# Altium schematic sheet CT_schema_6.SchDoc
size 218 x 258 mm
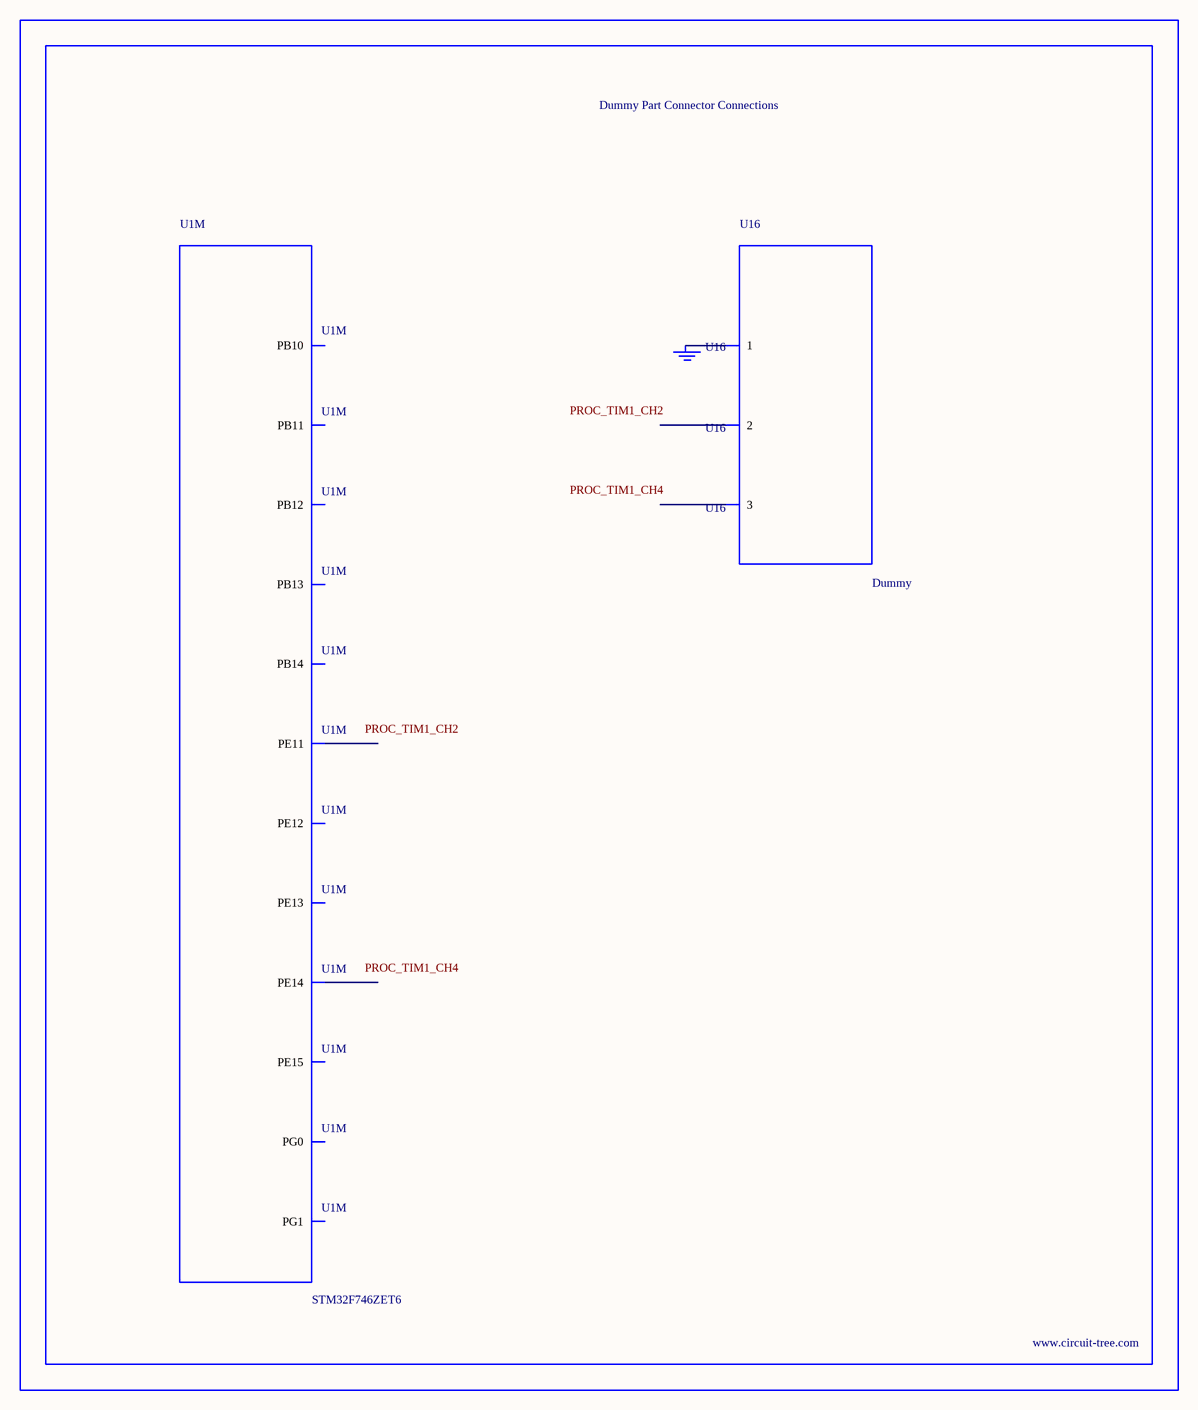
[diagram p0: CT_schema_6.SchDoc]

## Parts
BORDER5  (no value)
GND_INSTANCE_5_0  (no value)
U1  STM32F746ZET6  [LQFP144]  (part M of 13)
U16  Dummy  [DUMMY_PACKAGE_199]

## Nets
NetGND_INSTANCE_5_0_0: GND_INSTANCE_5_0.0(GND) U16.1

Not connected (* = marked no-connect by the designer): U1 56(PG0) 57(PG1) 64(PE11) 65(PE12) 66(PE13) 67(PE14) 68(PE15) 69(PB10) 70(PB11) 73(PB12) 74(PB13) 75(PB14); U16 2 3

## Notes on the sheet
- Labels drawn without touching a wire or pin: PROC_TIM1_CH2, PROC_TIM1_CH4

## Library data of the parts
BORDER5 = BORDER_PAGE5
GND_INSTANCE_5_0 = GND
